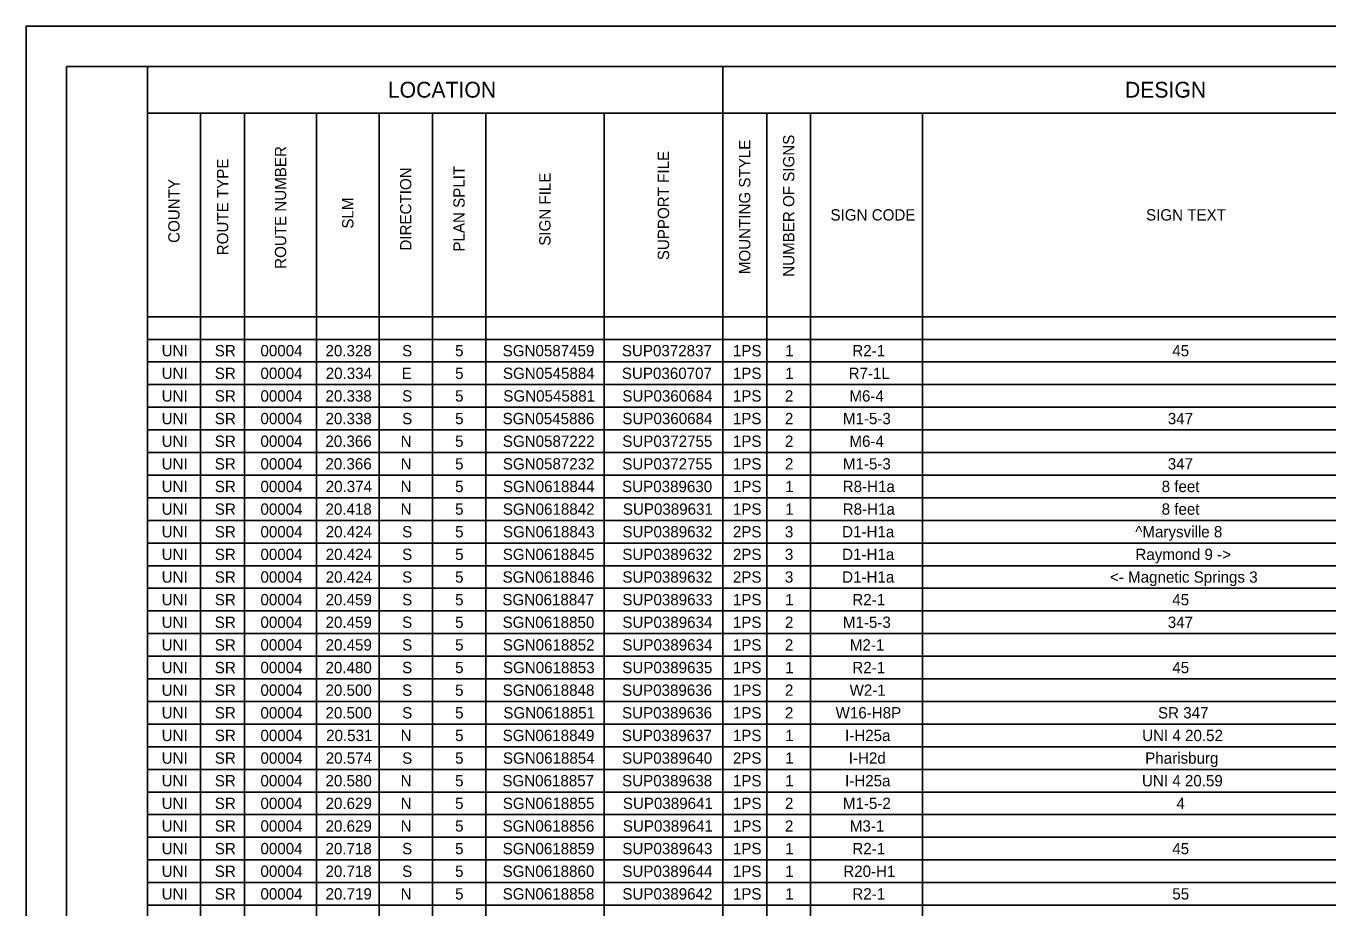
# Model space of a CAD drawing. Extents: x 0 to 34, y 0 to 22.
# Drawn here: x 0 to 16.1, y 11.09 to 22 of the extents above; entities that cross this region are included whole.
import ezdxf

# ---------------------------------------------------------------- set-up
doc = ezdxf.new("R2010")
doc.units = 0
for name, color, linetype in [('SH_Border', 7, 'Continuous'), ('SH_Cut_Line', 7, 'Continuous'), ('SH_Data', 7, 'Continuous'), ('SH_Text', 7, 'Continuous')]:
    doc.layers.add(name, color=color, linetype=linetype)

msp = doc.modelspace()

# ---------------------------------------------------------------- linework, layer by layer
at = {"layer": 'SH_Border'}
for points in [[(0.5, 21.5), (1.5, 21.5), (1.5, 0.5), (0.5, 0.5)], [(1.5, 21.5), (33.5, 21.5), (33.5, 0.5), (1.5, 0.5)]]:
    msp.add_lwpolyline(points, close=True, dxfattribs=at)
at = {"layer": 'SH_Cut_Line'}
msp.add_lwpolyline([(0, 0), (34, 0), (34, 22), (0, 22)], close=True, dxfattribs=at)
at = {"layer": 'SH_Data'}
for p, q in [((1.5, 21.5), (32.004, 21.5)), ((8.615, 21.5), (8.615, 0.764)), ((1.5, 20.924), (28.232, 20.924)), ((1.5, 20.924), (1.5, 0.764)), ((2.159, 20.924), (2.159, 0.764)), ((2.702, 20.924), (2.702, 0.764)), ((3.592, 20.924), (3.592, 0.764)), ((4.366, 20.924), (4.366, 0.764)), ((5.025, 20.924), (5.025, 0.764)), ((5.684, 20.924), (5.684, 0.764)), ((7.149, 20.924), (7.149, 0.764)), ((9.159, 20.924), (9.159, 0.764)), ((9.702, 20.924), (9.702, 0.764)), ((11.086, 20.924), (11.086, 0.764)), ((1.5, 18.404), (32.004, 18.404)), ((1.5, 18.124), (32.004, 18.124)), ((1.5, 17.844), (32.004, 17.844)), ((1.5, 17.564), (32.004, 17.564)), ((1.5, 17.284), (32.004, 17.284)), ((1.5, 17.004), (32.004, 17.004)), ((1.5, 16.724), (32.004, 16.724)), ((1.5, 16.444), (32.004, 16.444)), ((1.5, 16.164), (32.004, 16.164)), ((1.5, 15.884), (32.004, 15.884)), ((1.5, 15.604), (32.004, 15.604)), ((1.5, 15.324), (32.004, 15.324)), ((1.5, 15.044), (32.004, 15.044)), ((1.5, 14.764), (32.004, 14.764)), ((1.5, 14.484), (32.004, 14.484)), ((1.5, 14.204), (32.004, 14.204)), ((1.5, 13.924), (32.004, 13.924)), ((1.5, 13.644), (32.004, 13.644)), ((1.5, 13.364), (32.004, 13.364)), ((1.5, 13.084), (32.004, 13.084)), ((1.5, 12.804), (32.004, 12.804)), ((1.5, 12.524), (32.004, 12.524)), ((1.5, 12.244), (32.004, 12.244)), ((1.5, 11.964), (32.004, 11.964)), ((1.5, 11.684), (32.004, 11.684)), ((1.5, 11.404), (32.004, 11.404)), ((1.5, 11.124), (32.004, 11.124))]:
    msp.add_line(p, q, dxfattribs=at)

# ---------------------------------------------------------------- texts
at = {"layer": 'SH_Text'}
for s, height, p in [('LOCATION', 0.196, (4.474, 21.114)), ('DESIGN', 0.196, (13.589, 21.114)), ('SIGN CODE', 0.14, (9.948, 19.594)), ('SIGN TEXT', 0.14, (13.85, 19.594)), ('UNI', 0.14, (1.677, 17.914)), ('SR', 0.14, (2.334, 17.914)), ('00004', 0.14, (2.899, 17.914)), ('20.328', 0.14, (3.703, 17.914)), ('S', 0.14, (4.651, 17.914)), ('5', 0.14, (5.306, 17.914)), ('SGN0587459', 0.14, (5.894, 17.914)), ('SUP0372837', 0.14, (7.368, 17.914)), ('1PS', 0.14, (8.741, 17.914)), ('1', 0.14, (9.389, 17.914)), ('R2-1', 0.14, (10.218, 17.914)), ('45', 0.14, (14.175, 17.914)), ('UNI', 0.14, (1.677, 17.634)), ('SR', 0.14, (2.334, 17.634)), ('00004', 0.14, (2.899, 17.634)), ('20.334', 0.14, (3.706, 17.634)), ('E', 0.14, (4.645, 17.634)), ('5', 0.14, (5.306, 17.634)), ('SGN0545884', 0.14, (5.897, 17.634)), ('SUP0360707', 0.14, (7.368, 17.634)), ('1PS', 0.14, (8.741, 17.634)), ('1', 0.14, (9.389, 17.634)), ('R7-1L', 0.14, (10.172, 17.634)), ('UNI', 0.14, (1.677, 17.354)), ('SR', 0.14, (2.334, 17.354)), ('00004', 0.14, (2.899, 17.354)), ('20.338', 0.14, (3.703, 17.354)), ('S', 0.14, (4.651, 17.354)), ('5', 0.14, (5.306, 17.354)), ('SGN0545881', 0.14, (5.902, 17.354)), ('SUP0360684', 0.14, (7.374, 17.354)), ('1PS', 0.14, (8.741, 17.354)), ('2', 0.14, (9.384, 17.354)), ('M6-4', 0.14, (10.182, 17.354)), ('UNI', 0.14, (1.677, 17.074)), ('SR', 0.14, (2.334, 17.074)), ('00004', 0.14, (2.899, 17.074)), ('20.338', 0.14, (3.703, 17.074)), ('S', 0.14, (4.651, 17.074)), ('5', 0.14, (5.306, 17.074)), ('SGN0545886', 0.14, (5.893, 17.074)), ('SUP0360684', 0.14, (7.374, 17.074)), ('1PS', 0.14, (8.741, 17.074)), ('2', 0.14, (9.384, 17.074)), ('M1-5-3', 0.14, (10.101, 17.074)), ('347', 0.14, (14.119, 17.074)), ('UNI', 0.14, (1.677, 16.794)), ('SR', 0.14, (2.334, 16.794)), ('00004', 0.14, (2.899, 16.794)), ('20.366', 0.14, (3.702, 16.794)), ('N', 0.14, (4.632, 16.794)), ('5', 0.14, (5.306, 16.794)), ('SGN0587222', 0.14, (5.896, 16.794)), ('SUP0372755', 0.14, (7.373, 16.794)), ('1PS', 0.14, (8.741, 16.794)), ('2', 0.14, (9.384, 16.794)), ('M6-4', 0.14, (10.182, 16.794)), ('UNI', 0.14, (1.677, 16.514)), ('SR', 0.14, (2.334, 16.514)), ('00004', 0.14, (2.899, 16.514)), ('20.366', 0.14, (3.702, 16.514)), ('N', 0.14, (4.632, 16.514)), ('5', 0.14, (5.306, 16.514)), ('SGN0587232', 0.14, (5.896, 16.514)), ('SUP0372755', 0.14, (7.373, 16.514)), ('1PS', 0.14, (8.741, 16.514)), ('2', 0.14, (9.384, 16.514)), ('M1-5-3', 0.14, (10.101, 16.514)), ('347', 0.14, (14.119, 16.514)), ('UNI', 0.14, (1.677, 16.234)), ('SR', 0.14, (2.334, 16.234)), ('00004', 0.14, (2.899, 16.234)), ('20.374', 0.14, (3.706, 16.234)), ('N', 0.14, (4.632, 16.234)), ('5', 0.14, (5.306, 16.234)), ('SGN0618844', 0.14, (5.897, 16.234)), ('SUP0389630', 0.14, (7.371, 16.234)), ('1PS', 0.14, (8.741, 16.234)), ('1', 0.14, (9.389, 16.234)), ('R8-H1a', 0.14, (10.099, 16.234)), ('8 feet', 0.14, (14.043, 16.234)), ('8 feet', 0.14, (14.043, 15.954)), ('UNI', 0.14, (1.677, 15.954)), ('SR', 0.14, (2.334, 15.954)), ('00004', 0.14, (2.899, 15.954)), ('20.418', 0.14, (3.703, 15.954)), ('N', 0.14, (4.632, 15.954)), ('5', 0.14, (5.306, 15.954)), ('SGN0618842', 0.14, (5.896, 15.954)), ('SUP0389631', 0.14, (7.38, 15.954)), ('1PS', 0.14, (8.741, 15.954)), ('1', 0.14, (9.389, 15.954)), ('R8-H1a', 0.14, (10.099, 15.954)), ('UNI', 0.14, (1.677, 15.674)), ('SR', 0.14, (2.334, 15.674)), ('00004', 0.14, (2.899, 15.674)), ('20.424', 0.14, (3.706, 15.674)), ('S', 0.14, (4.651, 15.674)), ('5', 0.14, (5.306, 15.674)), ('SGN0618843', 0.14, (5.897, 15.674)), ('SUP0389632', 0.14, (7.374, 15.674)), ('2PS', 0.14, (8.741, 15.674)), ('3', 0.14, (9.384, 15.674)), ('D1-H1a', 0.14, (10.092, 15.674)), ('^ Marysville 8', 0.14, (13.717, 15.674)), ('UNI', 0.14, (1.677, 15.394)), ('SR', 0.14, (2.334, 15.394)), ('00004', 0.14, (2.899, 15.394)), ('20.424', 0.14, (3.706, 15.394)), ('S', 0.14, (4.651, 15.394)), ('5', 0.14, (5.306, 15.394)), ('SGN0618845', 0.14, (5.895, 15.394)), ('SUP0389632', 0.14, (7.374, 15.394)), ('2PS', 0.14, (8.741, 15.394)), ('3', 0.14, (9.384, 15.394)), ('D1-H1a', 0.14, (10.092, 15.394)), ('Raymond 9 ->', 0.14, (13.719, 15.394)), ('UNI', 0.14, (1.677, 15.114)), ('SR', 0.14, (2.334, 15.114)), ('00004', 0.14, (2.899, 15.114)), ('20.424', 0.14, (3.706, 15.114)), ('S', 0.14, (4.651, 15.114)), ('5', 0.14, (5.306, 15.114)), ('SGN0618846', 0.14, (5.893, 15.114)), ('SUP0389632', 0.14, (7.374, 15.114)), ('2PS', 0.14, (8.741, 15.114)), ('3', 0.14, (9.384, 15.114)), ('D1-H1a', 0.14, (10.092, 15.114)), ('<- Magnetic Springs 3', 0.14, (13.404, 15.114)), ('UNI', 0.14, (1.677, 14.834)), ('SR', 0.14, (2.334, 14.834)), ('00004', 0.14, (2.899, 14.834)), ('20.459', 0.14, (3.704, 14.834)), ('S', 0.14, (4.651, 14.834)), ('5', 0.14, (5.306, 14.834)), ('SGN0618847', 0.14, (5.89, 14.834)), ('SUP0389633', 0.14, (7.374, 14.834)), ('1PS', 0.14, (8.741, 14.834)), ('1', 0.14, (9.389, 14.834)), ('R2-1', 0.14, (10.218, 14.834)), ('45', 0.14, (14.175, 14.834)), ('UNI', 0.14, (1.677, 14.554)), ('SR', 0.14, (2.334, 14.554)), ('00004', 0.14, (2.899, 14.554)), ('20.459', 0.14, (3.704, 14.554)), ('S', 0.14, (4.651, 14.554)), ('5', 0.14, (5.306, 14.554)), ('SGN0618850', 0.14, (5.893, 14.554)), ('SUP0389634', 0.14, (7.374, 14.554)), ('1PS', 0.14, (8.741, 14.554)), ('2', 0.14, (9.384, 14.554)), ('M1-5-3', 0.14, (10.101, 14.554)), ('347', 0.14, (14.119, 14.554)), ('UNI', 0.14, (1.677, 14.274)), ('SR', 0.14, (2.334, 14.274)), ('00004', 0.14, (2.899, 14.274)), ('20.459', 0.14, (3.704, 14.274)), ('S', 0.14, (4.651, 14.274)), ('5', 0.14, (5.306, 14.274)), ('SGN0618852', 0.14, (5.896, 14.274)), ('SUP0389634', 0.14, (7.374, 14.274)), ('1PS', 0.14, (8.741, 14.274)), ('2', 0.14, (9.384, 14.274)), ('M2-1', 0.14, (10.187, 14.274)), ('UNI', 0.14, (1.677, 13.994)), ('SR', 0.14, (2.334, 13.994)), ('00004', 0.14, (2.899, 13.994)), ('20.480', 0.14, (3.703, 13.994)), ('S', 0.14, (4.651, 13.994)), ('5', 0.14, (5.306, 13.994)), ('SGN0618853', 0.14, (5.897, 13.994)), ('SUP0389635', 0.14, (7.373, 13.994)), ('1PS', 0.14, (8.741, 13.994)), ('1', 0.14, (9.389, 13.994)), ('R2-1', 0.14, (10.218, 13.994)), ('45', 0.14, (14.175, 13.994)), ('UNI', 0.14, (1.677, 13.714)), ('SR', 0.14, (2.334, 13.714)), ('00004', 0.14, (2.899, 13.714)), ('20.500', 0.14, (3.703, 13.714)), ('S', 0.14, (4.651, 13.714)), ('5', 0.14, (5.306, 13.714)), ('SGN0618848', 0.14, (5.894, 13.714)), ('SUP0389636', 0.14, (7.37, 13.714)), ('1PS', 0.14, (8.741, 13.714)), ('2', 0.14, (9.384, 13.714)), ('W2-1', 0.14, (10.184, 13.714)), ('UNI', 0.14, (1.677, 13.434)), ('SR', 0.14, (2.334, 13.434)), ('00004', 0.14, (2.899, 13.434)), ('20.500', 0.14, (3.703, 13.434)), ('S', 0.14, (4.651, 13.434)), ('5', 0.14, (5.306, 13.434)), ('SGN0618851', 0.14, (5.902, 13.434)), ('SUP0389636', 0.14, (7.37, 13.434)), ('1PS', 0.14, (8.741, 13.434)), ('2', 0.14, (9.384, 13.434)), ('W16-H8P', 0.14, (10.011, 13.434)), ('SR 347', 0.14, (13.998, 13.434)), ('UNI', 0.14, (1.677, 13.154)), ('SR', 0.14, (2.334, 13.154)), ('00004', 0.14, (2.899, 13.154)), ('20.531', 0.14, (3.711, 13.154)), ('N', 0.14, (4.632, 13.154)), ('5', 0.14, (5.306, 13.154)), ('SGN0618849', 0.14, (5.894, 13.154)), ('SUP0389637', 0.14, (7.368, 13.154)), ('1PS', 0.14, (8.741, 13.154)), ('1', 0.14, (9.389, 13.154)), ('I-H25a', 0.14, (10.128, 13.154)), ('UNI 4 20.52', 0.14, (13.802, 13.154)), ('UNI', 0.14, (1.677, 12.874)), ('SR', 0.14, (2.334, 12.874)), ('00004', 0.14, (2.899, 12.874)), ('20.574', 0.14, (3.706, 12.874)), ('S', 0.14, (4.651, 12.874)), ('5', 0.14, (5.306, 12.874)), ('SGN0618854', 0.14, (5.897, 12.874)), ('SUP0389640', 0.14, (7.371, 12.874)), ('2PS', 0.14, (8.741, 12.874)), ('1', 0.14, (9.389, 12.874)), ('I-H2d', 0.14, (10.174, 12.874)), ('Pharisburg', 0.14, (13.84, 12.874)), ('UNI', 0.14, (1.677, 12.594)), ('SR', 0.14, (2.334, 12.594)), ('00004', 0.14, (2.899, 12.594)), ('20.580', 0.14, (3.703, 12.594)), ('N', 0.14, (4.632, 12.594)), ('5', 0.14, (5.306, 12.594)), ('SGN0618857', 0.14, (5.89, 12.594)), ('SUP0389638', 0.14, (7.371, 12.594)), ('1PS', 0.14, (8.741, 12.594)), ('1', 0.14, (9.389, 12.594)), ('I-H25a', 0.14, (10.128, 12.594)), ('UNI 4 20.59', 0.14, (13.8, 12.594)), ('UNI', 0.14, (1.677, 12.314)), ('SR', 0.14, (2.334, 12.314)), ('00004', 0.14, (2.899, 12.314)), ('20.629', 0.14, (3.704, 12.314)), ('N', 0.14, (4.632, 12.314)), ('5', 0.14, (5.306, 12.314)), ('SGN0618855', 0.14, (5.895, 12.314)), ('SUP0389641', 0.14, (7.38, 12.314)), ('1PS', 0.14, (8.741, 12.314)), ('2', 0.14, (9.384, 12.314)), ('M1-5-2', 0.14, (10.101, 12.314)), ('4', 0.14, (14.226, 12.314)), ('UNI', 0.14, (1.677, 12.034)), ('SR', 0.14, (2.334, 12.034)), ('00004', 0.14, (2.899, 12.034)), ('20.629', 0.14, (3.704, 12.034)), ('N', 0.14, (4.632, 12.034)), ('5', 0.14, (5.306, 12.034)), ('SGN0618856', 0.14, (5.893, 12.034)), ('SUP0389641', 0.14, (7.38, 12.034)), ('1PS', 0.14, (8.741, 12.034)), ('2', 0.14, (9.384, 12.034)), ('M3-1', 0.14, (10.187, 12.034)), ('UNI', 0.14, (1.677, 11.754)), ('SR', 0.14, (2.334, 11.754)), ('00004', 0.14, (2.899, 11.754)), ('20.718', 0.14, (3.703, 11.754)), ('S', 0.14, (4.651, 11.754)), ('5', 0.14, (5.306, 11.754)), ('SGN0618859', 0.14, (5.894, 11.754)), ('SUP0389643', 0.14, (7.374, 11.754)), ('1PS', 0.14, (8.741, 11.754)), ('1', 0.14, (9.389, 11.754)), ('R2-1', 0.14, (10.218, 11.754)), ('45', 0.14, (14.175, 11.754)), ('UNI', 0.14, (1.677, 11.474)), ('SR', 0.14, (2.334, 11.474)), ('00004', 0.14, (2.899, 11.474)), ('20.718', 0.14, (3.703, 11.474)), ('S', 0.14, (4.651, 11.474)), ('5', 0.14, (5.306, 11.474)), ('SGN0618860', 0.14, (5.893, 11.474)), ('SUP0389644', 0.14, (7.374, 11.474)), ('1PS', 0.14, (8.741, 11.474)), ('1', 0.14, (9.389, 11.474)), ('R20-H1', 0.14, (10.106, 11.474)), ('UNI', 0.14, (1.677, 11.194)), ('SR', 0.14, (2.334, 11.194)), ('00004', 0.14, (2.899, 11.194)), ('20.719', 0.14, (3.704, 11.194)), ('N', 0.14, (4.632, 11.194)), ('5', 0.14, (5.306, 11.194)), ('SGN0618858', 0.14, (5.894, 11.194)), ('SUP0389642', 0.14, (7.374, 11.194)), ('1PS', 0.14, (8.741, 11.194)), ('1', 0.14, (9.389, 11.194)), ('R2-1', 0.14, (10.218, 11.194)), ('55', 0.14, (14.175, 11.194))]:
    msp.add_text(s, height=height, dxfattribs=at).set_placement(p)
for s, p in [('NUMBER OF SIGNS', (9.501, 18.898)), ('ROUTE NUMBER', (3.217, 18.996)), ('SUPPORT FILE', (7.952, 19.103)), ('MOUNTING STYLE', (8.957, 18.93)), ('ROUTE TYPE', (2.501, 19.164)), ('DIRECTION', (4.765, 19.222)), ('PLAN SPLIT', (5.424, 19.209)), ('SIGN FILE', (6.486, 19.282)), ('COUNTY', (1.899, 19.317)), ('SLM', (4.049, 19.493))]:
    msp.add_text(s, height=0.14, rotation=90, dxfattribs=at).set_placement(p)

doc.saveas('drawing.dxf')
